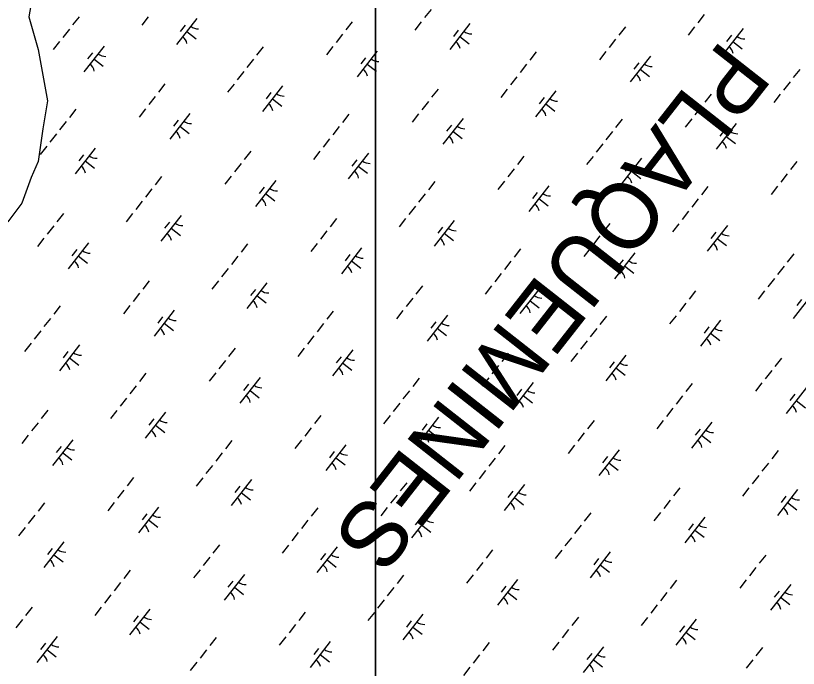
# Model space of a CAD drawing. Extents: x 3896831 to 3918110, y 171006 to 193349.
# Drawn here: x 3905430 to 3906624, y 183084 to 184079 of the extents above; entities that cross this region are included whole.
import ezdxf

# ---------------------------------------------------------------- set-up
doc = ezdxf.new("R2010")
doc.units = 0
doc.layers.add('V-TOPO-GNAM-IDEN', color=7, linetype='Continuous')
doc.layers.add('V-WETL-SWMP', color=7, linetype='Continuous')

msp = doc.modelspace()

# ---------------------------------------------------------------- linework, layer by layer
at = {"layer": 'V-WETL-SWMP'}
for p, q in [((3905979.3, 184854.9), (3905979.3, 179465.2)), ((3905979.3, 179465.2), (3905979.3, 184854.9)), ((3905464.4, 184162), (3905450.2, 184076.8)), ((3906063.8, 184088.2), (3906054, 184075.6)), ((3905450.2, 184076.8), (3905464.4, 184027)), ((3905526.9, 184077.1), (3905517.1, 184064.5)), ((3905632.4, 184077), (3905622.5, 184064.4)), ((3906480.5, 184080.5), (3906470.6, 184067.9)), ((3905706.5, 184074.3), (3905675.7, 184034.9)), ((3905688.7, 184064.1), (3905681.3, 184054.6)), ((3905943.6, 184069.4), (3905933.7, 184056.8)), ((3906049, 184069.3), (3906039.2, 184056.7)), ((3906123.2, 184066.6), (3906092.3, 184027.2)), ((3905512.1, 184058.2), (3905502.2, 184045.6)), ((3905691.1, 184054.6), (3905705.3, 184043.5)), ((3906105.4, 184056.4), (3906098, 184046.9)), ((3906360.2, 184061.7), (3906350.3, 184049.1)), ((3906465.7, 184061.6), (3906455.8, 184049)), ((3906539.8, 184058.9), (3906509, 184019.5)), ((3905928.8, 184050.5), (3905918.9, 184037.9)), ((3906107.7, 184046.9), (3906121.9, 184035.8)), ((3906345.4, 184042.8), (3906335.5, 184030.2)), ((3906522, 184048.7), (3906514.6, 184039.2)), ((3905497.3, 184039.3), (3905487.4, 184026.8)), ((3905565.1, 184032.3), (3905534.3, 183993)), ((3905807.7, 184031.1), (3905797.8, 184018.5)), ((3905914, 184031.6), (3905904.1, 184019.1)), ((3906524.4, 184039.2), (3906538.5, 184028.1)), ((3905464.4, 184027), (3905478.6, 183948.9)), ((3905547.3, 184022.1), (3905539.9, 184012.7)), ((3905979.3, 184021.5), (3905950.9, 183985.3)), ((3905981.8, 184024.6), (3905979.3, 184021.5)), ((3906224.4, 184023.4), (3906214.5, 184010.8)), ((3906330.6, 184023.9), (3906320.7, 184011.4)), ((3906398.4, 184016.9), (3906367.6, 183977.6)), ((3905549.7, 184012.6), (3905563.9, 184001.5)), ((3905792.9, 184012.2), (3905783, 183999.6)), ((3905964, 184014.4), (3905956.6, 184005)), ((3905966.3, 184004.9), (3905979.3, 183994.8)), ((3906209.6, 184004.5), (3906199.7, 183991.9)), ((3906380.6, 184006.7), (3906373.2, 183997.3)), ((3905778.1, 183993.3), (3905768.2, 183980.7)), ((3905979.3, 183994.8), (3905980.5, 183993.8)), ((3906383, 183997.2), (3906397.2, 183986.1)), ((3906626.2, 183996.8), (3906616.3, 183984.2)), ((3906194.7, 183985.6), (3906184.9, 183973)), ((3905657.8, 183974.5), (3905648, 183961.9)), ((3905763.3, 183974.4), (3905753.4, 183961.8)), ((3905837.4, 183971.7), (3905806.6, 183932.3)), ((3906611.4, 183977.9), (3906601.5, 183965.3)), ((3905819.6, 183961.5), (3905812.2, 183952)), ((3906074.5, 183966.8), (3906064.6, 183954.2)), ((3906179.9, 183966.7), (3906170.1, 183954.1)), ((3906254.1, 183964), (3906223.2, 183924.6)), ((3906491.1, 183959.1), (3906481.3, 183946.5)), ((3906596.6, 183959), (3906586.7, 183946.4)), ((3905478.6, 183948.9), (3905471.5, 183906.3)), ((3905643, 183955.6), (3905633.2, 183943)), ((3905822, 183952), (3905836.2, 183940.9)), ((3906059.7, 183947.9), (3906049.8, 183935.3)), ((3906236.3, 183953.8), (3906228.9, 183944.3)), ((3905522, 183936.1), (3905512.1, 183923.6)), ((3905628.2, 183936.7), (3905618.4, 183924.1)), ((3906238.7, 183944.3), (3906252.8, 183933.2)), ((3906476.3, 183940.2), (3906466.4, 183927.6)), ((3905696, 183929.7), (3905665.2, 183890.3)), ((3905938.6, 183928.4), (3905928.8, 183915.9)), ((3906044.9, 183929), (3906035, 183916.4)), ((3906112.7, 183922), (3906081.8, 183882.6)), ((3906355.3, 183920.7), (3906345.4, 183908.2)), ((3906461.5, 183921.3), (3906451.6, 183908.7)), ((3905507.2, 183917.3), (3905497.3, 183904.7)), ((3905678.3, 183919.5), (3905670.8, 183910.1)), ((3905680.6, 183910), (3905694.8, 183898.9)), ((3905923.8, 183909.6), (3905914, 183897)), ((3906094.9, 183911.8), (3906087.5, 183902.4)), ((3906529.3, 183914.3), (3906498.5, 183874.9)), ((3905471.5, 183906.3), (3905464.4, 183856.5)), ((3905492.4, 183898.4), (3905482.5, 183885.8)), ((3906097.3, 183902.3), (3906111.4, 183891.2)), ((3906340.5, 183901.9), (3906330.6, 183889.3)), ((3906511.5, 183904.1), (3906504.1, 183894.7)), ((3905909, 183890.7), (3905899.2, 183878.1)), ((3906513.9, 183894.6), (3906528.1, 183883.5)), ((3905477.6, 183879.5), (3905467.7, 183866.9)), ((3905551.7, 183876.7), (3905520.9, 183837.4)), ((3906325.7, 183883), (3906315.8, 183870.4)), ((3905533.9, 183866.5), (3905526.5, 183857.1)), ((3905788.8, 183871.9), (3905778.9, 183859.3)), ((3905894.2, 183871.8), (3905884.4, 183859.2)), ((3905968.4, 183869), (3905937.5, 183829.7)), ((3906205.4, 183864.2), (3906195.5, 183851.6)), ((3906310.9, 183864.1), (3906301, 183851.5)), ((3906385, 183861.3), (3906354.2, 183822)), ((3905464.4, 183856.5), (3905453.8, 183831.7)), ((3905536.3, 183857.1), (3905550.5, 183846)), ((3905774, 183853), (3905764.1, 183840.4)), ((3905950.6, 183858.8), (3905943.2, 183849.4)), ((3905952.9, 183849.4), (3905967.1, 183838.3)), ((3906367.2, 183851.1), (3906359.8, 183841.7)), ((3906622, 183856.5), (3906612.2, 183843.9)), ((3906190.6, 183845.3), (3906180.7, 183832.7)), ((3906369.6, 183841.7), (3906383.7, 183830.6)), ((3906607.2, 183837.6), (3906597.4, 183825)), ((3905453.8, 183831.7), (3905439.6, 183792.6)), ((3905652.9, 183833.5), (3905643, 183820.9)), ((3905759.1, 183834.1), (3905749.3, 183821.5)), ((3905827, 183827.1), (3905796.1, 183787.7)), ((3906069.6, 183825.8), (3906059.7, 183813.2)), ((3906175.8, 183826.4), (3906165.9, 183813.8)), ((3905638.1, 183814.6), (3905628.2, 183802.1)), ((3905809.2, 183816.9), (3905801.8, 183807.5)), ((3906243.6, 183819.4), (3906212.8, 183780)), ((3906486.2, 183818.1), (3906476.3, 183805.5)), ((3906592.4, 183818.7), (3906582.6, 183806.1)), ((3905811.5, 183807.4), (3905825.7, 183796.3)), ((3906054.7, 183806.9), (3906044.9, 183794.4)), ((3906225.8, 183809.2), (3906218.4, 183799.8)), ((3905439.6, 183792.6), (3905418.3, 183764.2)), ((3905623.3, 183795.8), (3905613.4, 183783.2)), ((3906228.2, 183799.7), (3906242.4, 183788.6)), ((3906471.4, 183799.2), (3906461.5, 183786.7)), ((3906039.9, 183788.1), (3906030.1, 183775.5)), ((3906456.6, 183780.4), (3906446.7, 183767.8)), ((3905503, 183777), (3905493.2, 183764.4)), ((3905608.5, 183776.9), (3905598.6, 183764.3)), ((3905682.6, 183774.1), (3905651.8, 183734.8)), ((3905919.7, 183769.3), (3905909.8, 183756.7)), ((3906025.1, 183769.2), (3906015.3, 183756.6)), ((3906099.3, 183766.4), (3906068.4, 183727.1)), ((3905488.2, 183758.1), (3905478.4, 183745.5)), ((3905664.8, 183763.9), (3905657.4, 183754.5)), ((3905667.2, 183754.5), (3905681.4, 183743.4)), ((3906081.5, 183756.2), (3906074.1, 183746.8)), ((3906336.3, 183761.6), (3906326.4, 183749)), ((3906441.8, 183761.5), (3906431.9, 183748.9)), ((3906515.9, 183758.7), (3906485.1, 183719.4)), ((3905904.9, 183750.4), (3905895, 183737.8)), ((3906083.9, 183746.8), (3906098, 183735.7)), ((3906321.5, 183742.7), (3906311.6, 183730.1)), ((3906498.1, 183748.5), (3906490.7, 183739.1)), ((3905473.4, 183739.2), (3905463.6, 183726.6)), ((3905541.2, 183732.2), (3905510.4, 183692.8)), ((3905783.8, 183730.9), (3905774, 183718.3)), ((3905890.1, 183731.5), (3905880.2, 183718.9)), ((3906500.5, 183739.1), (3906514.7, 183728)), ((3905523.4, 183722), (3905516, 183712.5)), ((3905957.9, 183724.5), (3905927, 183685.1)), ((3906200.5, 183723.2), (3906190.6, 183710.6)), ((3906306.7, 183723.8), (3906296.8, 183711.2)), ((3905525.8, 183712.5), (3905540, 183701.4)), ((3905769, 183712), (3905759.2, 183699.4)), ((3905940.1, 183714.3), (3905932.7, 183704.8)), ((3906374.5, 183716.8), (3906343.7, 183677.4)), ((3906356.7, 183706.6), (3906349.3, 183697.1)), ((3906617.1, 183715.5), (3906607.2, 183702.9)), ((3905942.5, 183704.8), (3905956.6, 183693.7)), ((3906185.7, 183704.3), (3906175.8, 183691.7)), ((3906359.1, 183697.1), (3906373.3, 183686)), ((3906602.3, 183696.6), (3906592.4, 183684)), ((3905754.2, 183693.2), (3905744.3, 183680.6)), ((3906170.9, 183685.5), (3906161, 183672.9)), ((3905634, 183674.4), (3905624.1, 183661.8)), ((3905739.4, 183674.3), (3905729.5, 183661.7)), ((3905813.5, 183671.5), (3905782.7, 183632.2)), ((3906587.5, 183677.8), (3906577.6, 183665.2)), ((3905795.8, 183661.3), (3905788.4, 183651.9)), ((3906050.6, 183666.7), (3906040.7, 183654.1)), ((3906156.1, 183666.6), (3906146.2, 183654)), ((3906230.2, 183663.8), (3906199.3, 183624.5)), ((3906467.2, 183659), (3906457.4, 183646.4)), ((3906572.7, 183658.9), (3906562.8, 183646.3)), ((3905619.1, 183655.5), (3905609.3, 183642.9)), ((3905798.1, 183651.8), (3905812.3, 183640.7)), ((3906035.8, 183647.8), (3906025.9, 183635.2)), ((3906212.4, 183653.6), (3906205, 183644.2)), ((3906646.8, 183656.1), (3906616, 183616.8)), ((3905498.1, 183636), (3905488.2, 183623.4)), ((3905604.3, 183636.6), (3905594.5, 183624)), ((3906214.8, 183644.1), (3906228.9, 183633)), ((3906452.4, 183640.1), (3906442.6, 183627.5)), ((3906629, 183645.9), (3906621.6, 183636.5)), ((3905672.2, 183629.6), (3905641.3, 183590.2)), ((3905914.7, 183628.3), (3905904.9, 183615.7)), ((3906021, 183628.9), (3906011.1, 183616.3)), ((3905483.3, 183617.1), (3905473.4, 183604.5)), ((3905654.4, 183619.4), (3905647, 183609.9)), ((3906088.8, 183621.9), (3906058, 183582.5)), ((3906071, 183611.7), (3906063.6, 183602.2)), ((3906331.4, 183620.6), (3906321.5, 183608)), ((3906437.6, 183621.2), (3906427.8, 183608.6)), ((3906505.4, 183614.2), (3906474.6, 183574.8)), ((3905656.7, 183609.9), (3905670.9, 183598.8)), ((3905899.9, 183609.4), (3905890.1, 183596.8)), ((3906073.4, 183602.2), (3906087.5, 183591.1)), ((3906316.6, 183601.7), (3906306.7, 183589.1)), ((3906487.7, 183604), (3906480.2, 183594.5)), ((3905468.5, 183598.2), (3905458.6, 183585.6)), ((3905885.1, 183590.5), (3905875.3, 183577.9)), ((3906490, 183594.5), (3906504.2, 183583.4)), ((3905453.7, 183579.4), (3905443.8, 183566.8)), ((3905527.8, 183576.6), (3905497, 183537.3)), ((3906301.8, 183582.8), (3906291.9, 183570.2)), ((3905510, 183566.4), (3905502.6, 183557)), ((3905764.9, 183571.8), (3905755, 183559.2)), ((3905870.3, 183571.7), (3905860.5, 183559.1)), ((3905944.5, 183568.9), (3905913.6, 183529.6)), ((3906181.5, 183564.1), (3906171.6, 183551.5)), ((3906287, 183564), (3906277.1, 183551.4)), ((3905512.4, 183556.9), (3905526.6, 183545.8)), ((3905750.1, 183552.9), (3905740.2, 183540.3)), ((3905926.7, 183558.7), (3905919.3, 183549.3)), ((3906361.1, 183561.2), (3906330.3, 183521.9)), ((3906343.3, 183551), (3906335.9, 183541.6)), ((3906598.2, 183556.4), (3906588.3, 183543.8)), ((3905929, 183549.2), (3905943.2, 183538.1)), ((3906166.7, 183545.2), (3906156.8, 183532.6)), ((3906345.7, 183541.5), (3906359.9, 183530.4)), ((3905629, 183533.4), (3905619.2, 183520.8)), ((3905735.3, 183534), (3905725.4, 183521.4)), ((3905803.1, 183527), (3905772.2, 183487.6)), ((3906583.4, 183537.5), (3906573.5, 183524.9)), ((3905785.3, 183516.8), (3905777.9, 183507.3)), ((3906045.7, 183525.7), (3906035.8, 183513.1)), ((3906151.9, 183526.3), (3906142, 183513.7)), ((3906219.7, 183519.3), (3906188.9, 183479.9)), ((3906462.3, 183518), (3906452.4, 183505.4)), ((3906568.5, 183518.6), (3906558.7, 183506)), ((3905614.2, 183514.5), (3905604.3, 183501.9)), ((3905787.7, 183507.3), (3905801.8, 183496.2)), ((3906030.9, 183506.8), (3906021, 183494.2)), ((3906201.9, 183509.1), (3906194.5, 183499.6)), ((3906636.4, 183511.6), (3906605.5, 183472.2)), ((3905599.4, 183495.6), (3905589.5, 183483)), ((3906204.3, 183499.6), (3906218.5, 183488.5)), ((3906447.5, 183499.1), (3906437.6, 183486.5)), ((3906618.6, 183501.4), (3906611.2, 183491.9)), ((3906620.9, 183491.9), (3906635.1, 183480.8)), ((3906016.1, 183487.9), (3906006.2, 183475.3)), ((3906432.7, 183480.2), (3906422.8, 183467.6)), ((3905479.1, 183476.9), (3905469.3, 183464.3)), ((3905584.6, 183476.7), (3905574.7, 183464.2)), ((3905658.7, 183474), (3905627.9, 183434.7)), ((3905895.8, 183469.2), (3905885.9, 183456.6)), ((3906001.3, 183469), (3905991.4, 183456.5)), ((3905464.3, 183458), (3905454.5, 183445.4)), ((3905640.9, 183463.8), (3905633.5, 183454.4)), ((3906075.4, 183466.3), (3906044.5, 183427)), ((3906057.6, 183456.1), (3906050.2, 183446.7)), ((3906312.4, 183461.5), (3906302.6, 183448.9)), ((3906417.9, 183461.3), (3906408, 183448.8)), ((3906492, 183458.6), (3906461.2, 183419.3)), ((3905643.3, 183454.3), (3905657.5, 183443.2)), ((3905881, 183450.3), (3905871.1, 183437.7)), ((3906060, 183446.6), (3906074.1, 183435.5)), ((3906474.2, 183448.4), (3906466.8, 183439)), ((3905449.5, 183439.1), (3905439.7, 183426.5)), ((3905517.4, 183432.1), (3905486.5, 183392.7)), ((3905866.2, 183431.4), (3905856.3, 183418.8)), ((3906297.6, 183442.6), (3906287.8, 183430)), ((3906476.6, 183438.9), (3906490.8, 183427.8)), ((3905499.6, 183421.9), (3905492.2, 183412.4)), ((3905759.9, 183430.8), (3905750.1, 183418.2)), ((3905934, 183424.4), (3905903.2, 183385)), ((3906176.6, 183423.1), (3906166.7, 183410.5)), ((3906282.8, 183423.7), (3906273, 183411.1)), ((3905501.9, 183412.4), (3905516.1, 183401.3)), ((3905745.1, 183411.9), (3905735.3, 183399.3)), ((3905916.2, 183414.2), (3905908.8, 183404.7)), ((3906350.6, 183416.7), (3906319.8, 183377.3)), ((3906593.2, 183415.4), (3906583.4, 183402.8)), ((3905918.6, 183404.7), (3905932.7, 183393.6)), ((3906161.8, 183404.2), (3906151.9, 183391.6)), ((3906332.8, 183406.5), (3906325.4, 183397)), ((3906335.2, 183397), (3906349.4, 183385.9)), ((3906578.4, 183396.5), (3906568.6, 183383.9)), ((3905730.3, 183393), (3905720.5, 183380.4)), ((3906147, 183385.3), (3906137.1, 183372.7)), ((3905610.1, 183374.3), (3905600.2, 183361.7)), ((3905715.5, 183374.1), (3905705.7, 183361.5)), ((3906563.6, 183377.6), (3906553.7, 183365)), ((3905789.7, 183371.4), (3905758.8, 183332)), ((3905771.9, 183361.2), (3905764.5, 183351.8)), ((3906026.7, 183366.6), (3906016.8, 183354)), ((3906132.2, 183366.4), (3906122.3, 183353.8)), ((3906206.3, 183363.7), (3906175.5, 183324.3)), ((3905595.3, 183355.4), (3905585.4, 183342.8)), ((3905774.2, 183351.7), (3905788.4, 183340.6)), ((3906011.9, 183347.7), (3906002, 183335.1)), ((3906188.5, 183353.5), (3906181.1, 183344.1)), ((3906443.3, 183358.9), (3906433.5, 183346.3)), ((3906548.8, 183358.7), (3906538.9, 183346.1)), ((3906622.9, 183356), (3906592.1, 183316.6)), ((3905474.2, 183335.9), (3905464.3, 183323.3)), ((3905580.5, 183336.5), (3905570.6, 183323.9)), ((3906190.9, 183344), (3906205, 183332.9)), ((3906428.5, 183340), (3906418.7, 183327.4)), ((3906605.2, 183345.8), (3906597.8, 183336.4)), ((3906607.5, 183336.3), (3906621.7, 183325.2)), ((3905648.3, 183329.5), (3905617.4, 183290.1)), ((3905890.9, 183328.2), (3905881, 183315.6)), ((3905997.1, 183328.8), (3905987.2, 183316.2)), ((3905459.4, 183317), (3905449.5, 183304.4)), ((3905630.5, 183319.3), (3905623.1, 183309.8)), ((3906064.9, 183321.8), (3906034.1, 183282.4)), ((3906307.5, 183320.5), (3906297.6, 183307.9)), ((3906413.7, 183321.1), (3906403.9, 183308.5)), ((3906481.6, 183314.1), (3906450.7, 183274.7)), ((3905632.8, 183309.8), (3905647, 183298.7)), ((3905876.1, 183309.3), (3905866.2, 183296.7)), ((3906047.1, 183311.6), (3906039.7, 183302.1)), ((3906049.5, 183302.1), (3906063.7, 183291)), ((3906292.7, 183301.6), (3906282.8, 183289)), ((3906463.8, 183303.9), (3906456.4, 183294.4)), ((3905444.6, 183298.1), (3905434.7, 183285.5)), ((3905861.3, 183290.4), (3905851.4, 183277.8)), ((3906466.1, 183294.4), (3906480.3, 183283.3)), ((3905503.9, 183276.5), (3905473.1, 183237.1)), ((3906277.9, 183282.7), (3906268, 183270.1)), ((3905486.1, 183266.3), (3905478.7, 183256.9)), ((3905741, 183271.7), (3905731.1, 183259.1)), ((3905846.4, 183271.5), (3905836.6, 183258.9)), ((3905920.6, 183268.8), (3905889.7, 183229.4)), ((3905488.5, 183256.8), (3905502.7, 183245.7)), ((3905726.2, 183252.8), (3905716.3, 183240.2)), ((3905902.8, 183258.6), (3905895.4, 183249.2)), ((3906157.6, 183264), (3906147.8, 183251.4)), ((3906263.1, 183263.8), (3906253.2, 183251.2)), ((3906337.2, 183261.1), (3906306.4, 183221.7)), ((3906574.3, 183256.3), (3906564.4, 183243.7)), ((3905905.2, 183249.1), (3905919.3, 183238)), ((3906142.8, 183245.1), (3906133, 183232.5)), ((3906319.4, 183250.9), (3906312, 183241.5)), ((3906321.8, 183241.4), (3906336, 183230.3)), ((3905605.1, 183233.3), (3905595.3, 183220.7)), ((3905711.4, 183233.9), (3905701.5, 183221.3)), ((3906559.5, 183237.4), (3906549.6, 183224.8)), ((3905779.2, 183226.8), (3905748.3, 183187.5)), ((3905761.4, 183216.6), (3905754, 183207.2)), ((3906021.8, 183225.6), (3906011.9, 183213)), ((3906128, 183226.2), (3906118.1, 183213.6)), ((3906195.8, 183219.1), (3906165, 183179.8)), ((3906438.4, 183217.9), (3906428.6, 183205.3)), ((3906544.7, 183218.5), (3906534.8, 183205.9)), ((3905590.3, 183214.4), (3905580.5, 183201.8)), ((3905763.8, 183207.2), (3905777.9, 183196.1)), ((3906007, 183206.7), (3905997.1, 183194.1)), ((3906178, 183208.9), (3906170.6, 183199.5)), ((3906612.5, 183211.4), (3906581.6, 183172.1)), ((3905575.5, 183195.5), (3905565.7, 183182.9)), ((3906180.4, 183199.5), (3906194.6, 183188.4)), ((3906423.6, 183199), (3906413.7, 183186.4)), ((3906594.7, 183201.2), (3906587.3, 183191.8)), ((3905992.2, 183187.8), (3905982.3, 183175.2)), ((3906597.1, 183191.8), (3906611.2, 183180.7)), ((3905455.3, 183176.7), (3905445.4, 183164.2)), ((3905560.7, 183176.6), (3905550.9, 183164)), ((3905634.9, 183173.9), (3905604, 183134.5)), ((3905871.9, 183169), (3905862, 183156.5)), ((3905977.4, 183168.9), (3905967.5, 183156.3)), ((3906408.8, 183180.1), (3906398.9, 183167.5)), ((3905440.5, 183157.9), (3905430.6, 183145.3)), ((3905617.1, 183163.7), (3905609.7, 183154.2)), ((3906051.5, 183166.2), (3906020.7, 183126.8)), ((3906288.5, 183161.3), (3906278.7, 183148.8)), ((3906394, 183161.2), (3906384.1, 183148.6)), ((3906468.1, 183158.5), (3906437.3, 183119.1)), ((3905619.4, 183154.2), (3905633.6, 183143.1)), ((3905857.1, 183150.2), (3905847.2, 183137.6)), ((3906033.7, 183156), (3906026.3, 183146.5)), ((3906036.1, 183146.5), (3906050.2, 183135.4)), ((3906450.3, 183148.3), (3906442.9, 183138.8)), ((3906273.7, 183142.5), (3906263.9, 183129.9)), ((3906452.7, 183138.8), (3906466.9, 183127.7)), ((3905493.5, 183131.9), (3905462.6, 183092.6)), ((3905475.7, 183121.7), (3905468.3, 183112.3)), ((3905736.1, 183130.7), (3905726.2, 183118.1)), ((3905842.3, 183131.3), (3905832.4, 183118.7)), ((3905910.1, 183124.2), (3905879.3, 183084.9)), ((3906152.7, 183123), (3906142.8, 183110.4)), ((3906258.9, 183123.6), (3906249.1, 183111)), ((3905478, 183112.3), (3905492.2, 183101.2)), ((3905721.2, 183111.8), (3905711.4, 183099.2)), ((3905892.3, 183114), (3905884.9, 183104.6)), ((3906326.8, 183116.5), (3906295.9, 183077.2)), ((3906569.3, 183115.3), (3906559.5, 183102.7)), ((3905894.7, 183104.6), (3905908.9, 183093.5)), ((3906137.9, 183104.1), (3906128, 183091.5)), ((3906309, 183106.3), (3906301.6, 183096.9)), ((3906311.3, 183096.9), (3906325.5, 183085.8)), ((3905706.4, 183092.9), (3905696.6, 183080.3)), ((3906123.1, 183085.2), (3906113.2, 183072.6)), ((3906554.5, 183096.4), (3906544.7, 183083.8))]:
    msp.add_line(p, q, dxfattribs=at)
for centre, start, end in [((3905708.3, 184076.2), 231.1403, 272.6839), ((3906125, 184068.5), 231.1403, 272.6839), ((3905674.2, 184032.7), 11.1403, 52.6839), ((3906541.6, 184060.8), 231.1403, 272.6839), ((3906090.9, 184025), 11.1403, 52.6839), ((3906507.5, 184017.3), 11.1403, 52.6839), ((3905566.9, 184034.2), 231.1403, 272.6839), ((3905532.9, 183990.7), 11.1403, 52.6839), ((3905983.6, 184026.5), 231.1403, 256.096), ((3905983.6, 184026.5), 256.096, 272.6839), ((3906400.2, 184018.8), 231.1403, 272.6839), ((3905949.5, 183983), 11.1403, 52.6839), ((3906366.1, 183975.3), 11.1403, 52.6839), ((3905839.2, 183973.6), 231.1403, 272.6839), ((3906255.9, 183965.9), 231.1403, 272.6839), ((3905805.2, 183930.1), 11.1403, 52.6839), ((3906221.8, 183922.4), 11.1403, 52.6839), ((3905697.8, 183931.6), 231.1403, 272.6839), ((3906114.5, 183923.9), 231.1403, 272.6839), ((3905663.8, 183888.1), 11.1403, 52.6839), ((3906531.1, 183916.2), 231.1403, 272.6839), ((3906080.4, 183880.4), 11.1403, 52.6839), ((3906497.1, 183872.7), 11.1403, 52.6839), ((3905553.5, 183878.7), 231.1403, 272.6839), ((3905519.4, 183835.2), 11.1403, 52.6839), ((3905970.2, 183871), 231.1403, 272.6839), ((3906386.8, 183863.3), 231.1403, 272.6839), ((3905936.1, 183827.5), 11.1403, 52.6839), ((3906352.7, 183819.8), 11.1403, 52.6839), ((3905828.8, 183829), 231.1403, 272.6839), ((3906245.4, 183821.3), 231.1403, 272.6839), ((3905794.7, 183785.5), 11.1403, 52.6839), ((3906211.3, 183777.8), 11.1403, 52.6839), ((3905684.4, 183776.1), 231.1403, 272.6839), ((3906101.1, 183768.4), 231.1403, 272.6839), ((3905650.4, 183732.6), 11.1403, 52.6839), ((3906517.7, 183760.7), 231.1403, 272.6839), ((3906067, 183724.9), 11.1403, 52.6839), ((3906483.6, 183717.2), 11.1403, 52.6839), ((3905543, 183734.1), 231.1403, 272.6839), ((3905959.7, 183726.4), 231.1403, 272.6839), ((3905509, 183690.6), 11.1403, 52.6839), ((3905925.6, 183682.9), 11.1403, 52.6839), ((3906376.3, 183718.7), 231.1403, 272.6839), ((3906342.3, 183675.2), 11.1403, 52.6839), ((3905815.4, 183673.4), 231.1403, 272.6839), ((3906232, 183665.7), 231.1403, 272.6839), ((3905781.3, 183630), 11.1403, 52.6839), ((3906197.9, 183622.3), 11.1403, 52.6839), ((3905674, 183631.5), 231.1403, 272.6839), ((3905639.9, 183588), 11.1403, 52.6839), ((3906090.6, 183623.8), 231.1403, 272.6839), ((3906507.2, 183616.1), 231.1403, 272.6839), ((3906056.5, 183580.3), 11.1403, 52.6839), ((3906473.2, 183572.6), 11.1403, 52.6839), ((3905529.6, 183578.5), 231.1403, 272.6839), ((3905946.3, 183570.8), 231.1403, 272.6839), ((3905495.6, 183535.1), 11.1403, 52.6839), ((3905912.2, 183527.4), 11.1403, 52.6839), ((3906362.9, 183563.1), 231.1403, 272.6839), ((3906328.8, 183519.7), 11.1403, 52.6839), ((3905804.9, 183528.9), 231.1403, 272.6839), ((3906221.5, 183521.2), 231.1403, 272.6839), ((3905770.8, 183485.4), 11.1403, 52.6839), ((3906187.4, 183477.7), 11.1403, 52.6839), ((3906604.1, 183470), 11.1403, 52.6839), ((3905660.5, 183475.9), 231.1403, 272.6839), ((3905626.5, 183432.4), 11.1403, 52.6839), ((3906077.2, 183468.2), 231.1403, 272.6839), ((3906493.8, 183460.5), 231.1403, 272.6839), ((3906043.1, 183424.7), 11.1403, 52.6839), ((3905519.2, 183434), 231.1403, 272.6839), ((3906459.8, 183417), 11.1403, 52.6839), ((3905935.8, 183426.3), 231.1403, 272.6839), ((3905485.1, 183390.5), 11.1403, 52.6839), ((3905901.7, 183382.8), 11.1403, 52.6839), ((3906352.4, 183418.6), 231.1403, 272.6839), ((3906318.4, 183375.1), 11.1403, 52.6839), ((3905791.5, 183373.3), 231.1403, 272.6839), ((3906208.1, 183365.6), 231.1403, 272.6839), ((3905757.4, 183329.8), 11.1403, 52.6839), ((3906174, 183322.1), 11.1403, 52.6839), ((3906624.8, 183357.9), 231.1403, 272.6839), ((3906590.7, 183314.4), 11.1403, 52.6839), ((3905650.1, 183331.4), 231.1403, 272.6839), ((3905616, 183287.9), 11.1403, 52.6839), ((3906066.7, 183323.7), 231.1403, 272.6839), ((3906483.4, 183316), 231.1403, 272.6839), ((3906032.6, 183280.2), 11.1403, 52.6839), ((3906449.3, 183272.5), 11.1403, 52.6839), ((3905505.7, 183278.4), 231.1403, 272.6839), ((3905922.4, 183270.7), 231.1403, 272.6839), ((3905471.7, 183234.9), 11.1403, 52.6839), ((3905888.3, 183227.2), 11.1403, 52.6839), ((3906339, 183263), 231.1403, 272.6839), ((3906304.9, 183219.5), 11.1403, 52.6839), ((3905781, 183228.8), 231.1403, 272.6839), ((3906197.6, 183221.1), 231.1403, 272.6839), ((3905746.9, 183185.3), 11.1403, 52.6839), ((3906614.3, 183213.4), 231.1403, 272.6839), ((3906163.6, 183177.6), 11.1403, 52.6839), ((3906580.2, 183169.9), 11.1403, 52.6839), ((3905636.7, 183175.8), 231.1403, 272.6839), ((3905602.6, 183132.3), 11.1403, 52.6839), ((3906053.3, 183168.1), 231.1403, 272.6839), ((3906469.9, 183160.4), 231.1403, 272.6839), ((3906019.2, 183124.6), 11.1403, 52.6839), ((3906435.9, 183116.9), 11.1403, 52.6839), ((3905495.3, 183133.9), 231.1403, 272.6839), ((3905911.9, 183126.2), 231.1403, 272.6839), ((3905461.2, 183090.4), 11.1403, 52.6839), ((3906328.6, 183118.5), 231.1403, 272.6839), ((3905877.8, 183082.7), 11.1403, 52.6839), ((3906294.5, 183075), 11.1403, 52.6839)]:
    msp.add_arc(centre, 17.6, start, end, dxfattribs=at)

# ---------------------------------------------------------------- texts
at = {"layer": 'V-TOPO-GNAM-IDEN'}
msp.add_text('PLAQUEMINES', height=100, rotation=231.8952, dxfattribs=at).set_placement((3906507.6, 184044.5))

doc.saveas('drawing.dxf')
